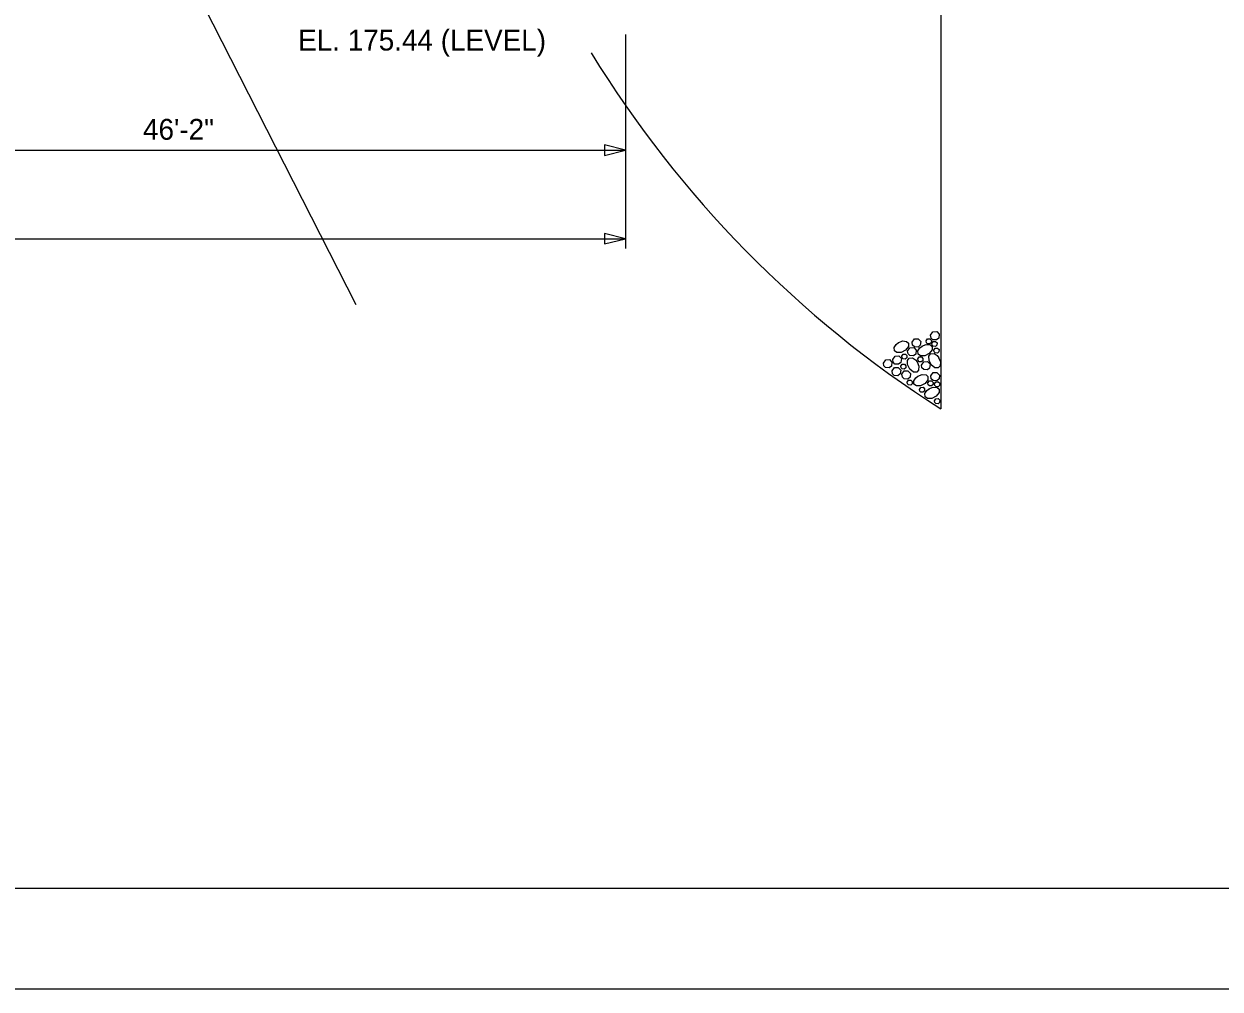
# Model space of a CAD drawing. Extents: x 471 to 2034, y -623 to 126.
# Drawn here: x 704.3 to 761.7, y -92.8 to -46.5 of the extents above; entities that cross this region are included whole.
import ezdxf

# ---------------------------------------------------------------- set-up
doc = ezdxf.new("R2010")
doc.units = 0
for name, color, linetype in [('Arrowhead Terminators CELL', 7, 'Continuous'), ('Auto Dimensioning', 7, 'Continuous'), ('Dimension Lines', 7, 'Continuous'), ('Exist Hydro Stream or Body of Water', 7, 'Continuous'), ('Miscellaneous Lines CELL', 7, 'Continuous'), ('Plan Sheet CELL', 7, 'Continuous'), ('Plot Shape CELL', 7, 'Continuous'), ('Sub End Bent Cap Lines CELL', 7, 'Continuous'), ('Sup Concrete Girder Lines', 7, 'Continuous'), ('Text', 7, 'Continuous')]:
    doc.layers.add(name, color=color, linetype=linetype)

# ---------------------------------------------------------------- blocks, each defined once
blk = doc.blocks.new('AH')
at = {"layer": 'Sub End Bent Cap Lines CELL'}
blk.add_lwpolyline([(0, 0), (-1.25, 0.312), (-1.25, -0.312)], close=True, dxfattribs=at)

msp = doc.modelspace()

# ---------------------------------------------------------------- linework, layer by layer
at = {"layer": 'Arrowhead Terminators CELL'}
msp.add_lwpolyline([(733.154, -52.568), (732.154, -52.318), (732.154, -52.818)], close=True, dxfattribs=at)
at = {"layer": 'Auto Dimensioning'}
for p, q in [((733.154, -47.015), (733.154, -57.285)), ((686.989, -52.568), (733.154, -52.568)), ((640.824, -56.82), (733.154, -56.82))]:
    msp.add_line(p, q, dxfattribs=at)
at = {"layer": 'Exist Hydro Stream or Body of Water'}
msp.add_lwpolyline([(720.234, -59.995), (712.935, -45.678), (708.822, -37.305), (707.974, -37.243), (707.877, -32.29), (701.705, -18.741)], dxfattribs=at)
at = {"layer": 'Miscellaneous Lines CELL'}
for points in [[(747.797, -61.445), (747.909, -61.285), (748.088, -61.275), (748.213, -61.404), (748.195, -61.585), (748.084, -61.677), (747.908, -61.664), (747.824, -61.583), (747.797, -61.445)], [(746.242, -61.81), (746.452, -61.726), (746.644, -61.743), (746.736, -61.83), (746.733, -61.986), (746.594, -62.164), (746.379, -62.271), (746.177, -62.275), (746.063, -62.194), (746.052, -62.033), (746.145, -61.889), (746.251, -61.804)], [(746.906, -61.789), (747.018, -61.63), (747.197, -61.62), (747.321, -61.748), (747.303, -61.929), (747.193, -62.021), (747.016, -62.008), (746.933, -61.928), (746.906, -61.789)], [(747.381, -61.979), (747.59, -61.896), (747.783, -61.913), (747.874, -62), (747.872, -62.156), (747.733, -62.333), (747.518, -62.441), (747.316, -62.444), (747.202, -62.363), (747.191, -62.202), (747.283, -62.058), (747.389, -61.974)], [(747.586, -61.724), (747.653, -61.628), (747.76, -61.622), (747.835, -61.699), (747.824, -61.808), (747.758, -61.863), (747.652, -61.855), (747.602, -61.807), (747.586, -61.724)], [(747.856, -61.847), (747.924, -61.751), (748.031, -61.745), (748.105, -61.822), (748.095, -61.931), (748.028, -61.986), (747.922, -61.978), (747.873, -61.93), (747.856, -61.847)], [(745.977, -62.611), (746.089, -62.451), (746.267, -62.441), (746.392, -62.57), (746.374, -62.751), (746.263, -62.843), (746.087, -62.83), (746.004, -62.749), (745.977, -62.611)], [(746.41, -62.453), (746.477, -62.357), (746.584, -62.351), (746.659, -62.429), (746.648, -62.537), (746.582, -62.592), (746.476, -62.584), (746.426, -62.536), (746.41, -62.453)], [(747.153, -62.723), (747.236, -62.933), (747.219, -63.125), (747.132, -63.217), (746.976, -63.214), (746.798, -63.075), (746.691, -62.86), (746.688, -62.658), (746.768, -62.544), (746.93, -62.534), (747.074, -62.626), (747.158, -62.732)], [(746.695, -62.211), (746.807, -62.051), (746.986, -62.041), (747.11, -62.17), (747.092, -62.351), (746.982, -62.443), (746.805, -62.43), (746.722, -62.349), (746.695, -62.211)], [(747.178, -62.586), (747.245, -62.49), (747.352, -62.484), (747.427, -62.562), (747.416, -62.67), (747.35, -62.725), (747.244, -62.718), (747.194, -62.669), (747.178, -62.586)], [(748.183, -62.518), (748.266, -62.727), (748.249, -62.92), (748.162, -63.011), (748.006, -63.008), (747.829, -62.869), (747.721, -62.655), (747.718, -62.453), (747.799, -62.339), (747.96, -62.328), (748.104, -62.42), (748.188, -62.526)], [(747.955, -62.165), (748.022, -62.069), (748.13, -62.063), (748.204, -62.14), (748.193, -62.249), (748.127, -62.304), (748.021, -62.296), (747.971, -62.248), (747.955, -62.165)], [(745.529, -62.786), (745.641, -62.626), (745.82, -62.616), (745.944, -62.745), (745.926, -62.926), (745.816, -63.018), (745.639, -63.005), (745.556, -62.924), (745.529, -62.786)], [(745.945, -63.164), (746.057, -63.005), (746.236, -62.995), (746.36, -63.124), (746.342, -63.304), (746.232, -63.396), (746.055, -63.383), (745.972, -63.303), (745.945, -63.164)], [(746.362, -62.937), (746.429, -62.842), (746.536, -62.836), (746.611, -62.913), (746.6, -63.021), (746.534, -63.076), (746.428, -63.069), (746.378, -63.02), (746.362, -62.937)], [(747.354, -62.882), (747.466, -62.722), (747.645, -62.712), (747.769, -62.841), (747.751, -63.022), (747.641, -63.114), (747.464, -63.101), (747.381, -63.02), (747.354, -62.882)], [(746.419, -63.322), (746.531, -63.163), (746.71, -63.153), (746.834, -63.282), (746.816, -63.462), (746.705, -63.554), (746.529, -63.542), (746.446, -63.461), (746.419, -63.322)], [(746.669, -63.701), (746.736, -63.605), (746.843, -63.599), (746.918, -63.677), (746.907, -63.785), (746.841, -63.84), (746.735, -63.833), (746.685, -63.784), (746.669, -63.701)], [(747.177, -63.416), (747.387, -63.333), (747.58, -63.35), (747.671, -63.437), (747.668, -63.593), (747.529, -63.77), (747.315, -63.878), (747.112, -63.881), (746.998, -63.8), (746.988, -63.639), (747.08, -63.495), (747.186, -63.411)], [(747.67, -63.741), (747.737, -63.645), (747.844, -63.639), (747.919, -63.717), (747.908, -63.825), (747.842, -63.88), (747.736, -63.873), (747.686, -63.824), (747.67, -63.741)], [(747.802, -63.401), (747.915, -63.242), (748.093, -63.232), (748.218, -63.361), (748.2, -63.541), (748.089, -63.633), (747.913, -63.621), (747.83, -63.54), (747.803, -63.401)], [(747.984, -63.779), (748.051, -63.684), (748.159, -63.678), (748.233, -63.755), (748.222, -63.863), (748.156, -63.919), (748.05, -63.911), (748, -63.863), (747.984, -63.779)], [(747.259, -64.05), (747.326, -63.954), (747.434, -63.948), (747.508, -64.026), (747.498, -64.134), (747.431, -64.189), (747.325, -64.181), (747.275, -64.133), (747.259, -64.05)], [(747.712, -64.025), (747.922, -63.942), (748.115, -63.958), (748.206, -64.045), (748.203, -64.202), (748.064, -64.379), (747.85, -64.486), (747.647, -64.49), (747.533, -64.409), (747.523, -64.248), (747.615, -64.104), (747.721, -64.019)], [(747.984, -64.595), (748.051, -64.499), (748.159, -64.493), (748.233, -64.571), (748.222, -64.679), (748.156, -64.734), (748.05, -64.727), (748, -64.678), (747.984, -64.595)]]:
    msp.add_lwpolyline(points, dxfattribs=at)
at = {"layer": 'Plan Sheet CELL'}
msp.add_line((575.848, -87.977), (831.85, -87.977), dxfattribs=at)
at = {"layer": 'Plot Shape CELL'}
msp.add_lwpolyline([(567.415, 83.173), (831.92, 83.173), (831.92, -92.826), (567.415, -92.826)], close=True, dxfattribs=at)
at = {"layer": 'Sup Concrete Girder Lines'}
msp.add_line((748.285, -39.429), (748.285, -64.986), dxfattribs=at)
msp.add_arc((777.095, -19.924), 53.484, 211.54506, 237.40766, dxfattribs=at)

# ---------------------------------------------------------------- block references
at = {"layer": 'Auto Dimensioning', "xscale": 0.8, "yscale": 0.8000000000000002}
msp.add_blockref('AH', (733.154, -56.82), dxfattribs=at)

# ---------------------------------------------------------------- texts
at = {"layer": 'Dimension Lines'}
msp.add_text('46\'-2"', height=1, dxfattribs=at).set_placement((710.005, -52.068))
at = {"layer": 'Text'}
msp.add_text('EL. 175.44 (LEVEL)', height=1, dxfattribs=at).set_placement((717.449, -47.787))

doc.saveas('drawing.dxf')
